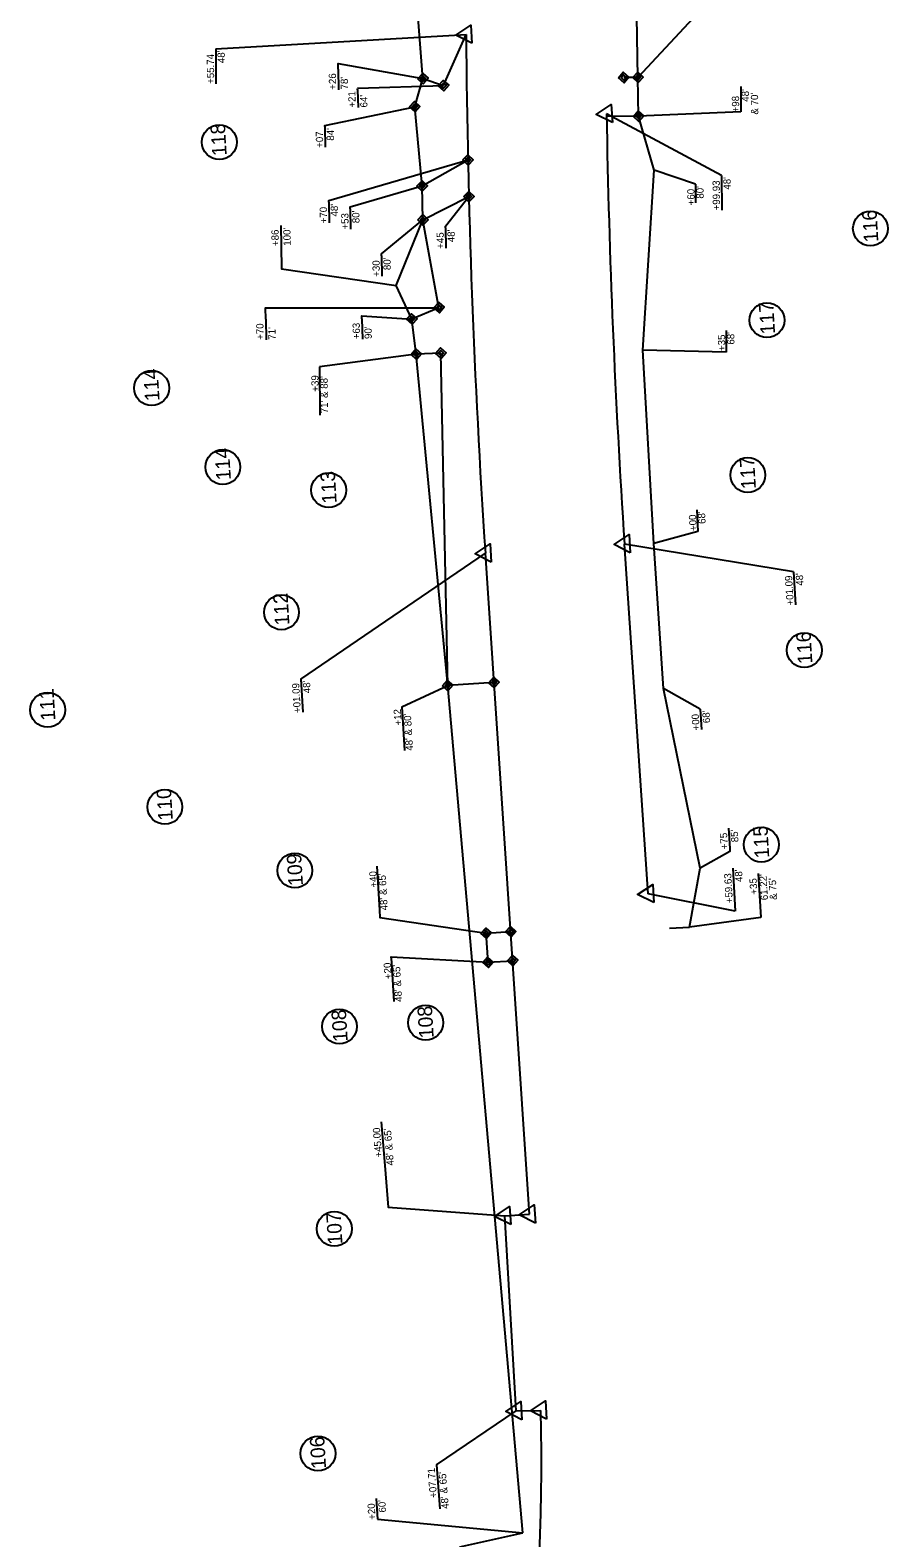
# Model space of a CAD drawing. Extents: x 2320946 to 2332748, y 597838 to 612698.
# Drawn here: x 2328037 to 2328627, y 604376 to 605414 of the extents above; entities that cross this region are included whole.
import ezdxf

# ---------------------------------------------------------------- set-up
doc = ezdxf.new("R2010")
doc.units = 0
for name, color, linetype in [('Prop Easement Construction', 7, 'Continuous'), ('Prop Easement Construction Station Offsets', 7, 'Continuous'), ('Prop Easement Permanent Drainage', 7, 'Continuous'), ('Prop Easement Permanent Drainage Station Offsets', 7, 'Continuous'), ('Prop Easement Permanent Drainage Utility', 7, 'Continuous'), ('Prop Easement Permanent Utility', 7, 'Continuous'), ('Prop Easement Permanent Utility Station Offsets', 7, 'Continuous'), ('Prop Parcel Number CELL', 7, 'Continuous'), ('Prop ROW Marker CELL', 7, 'Continuous'), ('Prop ROW Permanent Easement CELL', 7, 'Continuous'), ('Prop ROW RW Lines', 7, 'Continuous'), ('Prop ROW Station Offsets', 7, 'Continuous')]:
    doc.layers.add(name, color=color, linetype=linetype)

msp = doc.modelspace()

# ---------------------------------------------------------------- linework, layer by layer
at = {"layer": 'Prop Easement Construction'}
for p, q in [((2328455.1, 605381.6), (2328452.9, 605513.1)), ((2328307.1, 605380.8), (2328301.6, 605450.6)), ((2328466.3, 605317.6), (2328455.5, 605354.9)), ((2328458.5, 605193.8), (2328466.3, 605317.6)), ((2328209.2, 605279.6), (2328209.5, 605265.6)), ((2328288.6, 605238.2), (2328307.1, 605283.5)), ((2328299.4, 605215.2), (2328288.6, 605238.2)), ((2328324.1, 604962.9), (2328302.4, 605191)), ((2328465.9, 605060.6), (2328458.5, 605193.8)), ((2328472.6, 604960.8), (2328465.9, 605060.6)), ((2328375.8, 604379.4), (2328324.1, 604962.9)), ((2328497.9, 604837.2), (2328472.6, 604960.8)), ((2328490.5, 604796.6), (2328497.9, 604837.2)), ((2328476.8, 604795.7), (2328490.5, 604796.6)), ((2328332.4, 604369.8), (2328375.8, 604379.4))]:
    msp.add_line(p, q, dxfattribs=at)
msp.add_lwpolyline([(2328209.5, 605265.6), (2328209.8, 605249.7), (2328288.6, 605238.2)], dxfattribs=at)
at = {"layer": 'Prop Easement Construction Station Offsets'}
for p, q in [((2328494.6, 605308), (2328494.7, 605295.2)), ((2328515.7, 605207.4), (2328515.9, 605192.4)), ((2328515.9, 605192.4), (2328458.5, 605193.8)), ((2328495.5, 605083.9), (2328496.4, 605068.8)), ((2328496.4, 605068.8), (2328465.9, 605060.6)), ((2328498, 604946.6), (2328498.8, 604932.5)), ((2328517.5, 604864.6), (2328518.3, 604850.6)), ((2328537.8, 604833.4), (2328539.6, 604803.2)), ((2328274.9, 604403.1), (2328275.8, 604389))]:
    msp.add_line(p, q, dxfattribs=at)
for points in [[(2328494.6, 605308), (2328466.3, 605317.6)], [(2328498, 604946.6), (2328472.6, 604960.8)], [(2328518.3, 604850.6), (2328518.4, 604848.6), (2328497.9, 604837.2)], [(2328539.6, 604803.2), (2328490.5, 604796.6)], [(2328275.8, 604389), (2328375.8, 604379.4)]]:
    msp.add_lwpolyline(points, dxfattribs=at)
at = {"layer": 'Prop Easement Permanent Drainage'}
for p, q in [((2328455.1, 605381.6), (2328445.3, 605381.5)), ((2328455.5, 605354.9), (2328455.1, 605381.6)), ((2328455.5, 605354.9), (2328433.5, 605354.6)), ((2328350.5, 604792.3), (2328367.5, 604793.4)), ((2328351.9, 604772.3), (2328350.5, 604792.3)), ((2328351.9, 604772.3), (2328368.8, 604773.4))]:
    msp.add_line(p, q, dxfattribs=at)
at = {"layer": 'Prop Easement Permanent Drainage Station Offsets'}
for p, q in [((2328493, 605422.4), (2328455.1, 605381.6)), ((2328525.9, 605375.2), (2328526, 605357.9)), ((2328526, 605357.9), (2328455.5, 605354.9)), ((2328242.2, 605295.6), (2328242.4, 605281.4)), ((2328257, 605291), (2328257.2, 605277.1)), ((2328322.6, 605277.9), (2328322.8, 605263.9)), ((2328278.5, 605258.8), (2328278.7, 605244.6)), ((2328275.4, 604838.4), (2328277.2, 604808.3)), ((2328285.3, 604775.3), (2328287.1, 604745.2))]:
    msp.add_line(p, q, dxfattribs=at)
for points in [[(2328242.2, 605295.6), (2328242.2, 605296.8), (2328338.1, 605324.7)], [(2328257, 605291), (2328257, 605292.5), (2328306.5, 605306.8)], [(2328322.6, 605277.9), (2328322.6, 605279.1), (2328338.7, 605299.5)], [(2328278.5, 605258.8), (2328278.5, 605260.2), (2328307.1, 605283.5)], [(2328277.2, 604808.3), (2328277.5, 604803.2), (2328350.5, 604792.3)], [(2328285.3, 604775.3), (2328285.3, 604776.1), (2328351.9, 604772.3)]]:
    msp.add_lwpolyline(points, dxfattribs=at)
at = {"layer": 'Prop Easement Permanent Drainage Utility'}
for p, q in [((2328306.5, 605306.8), (2328338.1, 605324.7)), ((2328307.1, 605283.5), (2328306.5, 605306.8)), ((2328307.1, 605283.5), (2328338.7, 605299.5))]:
    msp.add_line(p, q, dxfattribs=at)
at = {"layer": 'Prop Easement Permanent Utility'}
for p, q in [((2328321.2, 605375.9), (2328336.8, 605411.1)), ((2328301.4, 605361.4), (2328307.1, 605380.8)), ((2328307.1, 605380.8), (2328321.2, 605375.9)), ((2328306.5, 605306.8), (2328301.4, 605361.4)), ((2328318.1, 605223), (2328307.1, 605283.5)), ((2328318.1, 605223), (2328299.4, 605215.2)), ((2328302.4, 605191), (2328299.4, 605215.2)), ((2328319.4, 605191.7), (2328302.4, 605191)), ((2328324.1, 604962.9), (2328319.4, 605191.7)), ((2328356, 604965), (2328324.1, 604962.9))]:
    msp.add_line(p, q, dxfattribs=at)
at = {"layer": 'Prop Easement Permanent Utility Station Offsets'}
for p, q in [((2328248.6, 605387.2), (2328248.9, 605373.1)), ((2328262.1, 605373.1), (2328262.4, 605360.8)), ((2328239.5, 605347.8), (2328239.7, 605333.6)), ((2328198.8, 605215.1), (2328199.1, 605200.9)), ((2328265.1, 605215.3), (2328265.4, 605201.4)), ((2328302.4, 605191), (2328235.8, 605182.2)), ((2328235.8, 605182.2), (2328236.1, 605148.9)), ((2328292.6, 604948.2), (2328294.4, 604918.1))]:
    msp.add_line(p, q, dxfattribs=at)
for points in [[(2328248.6, 605387.2), (2328248.6, 605391.1), (2328307.1, 605380.8)], [(2328262.1, 605373.1), (2328262.2, 605374.1), (2328321.2, 605375.9)], [(2328239.5, 605347.8), (2328239.5, 605348.4), (2328301.4, 605361.4)], [(2328198.8, 605215.1), (2328198.6, 605223), (2328318.1, 605223)], [(2328265.1, 605215.3), (2328265.1, 605217.5), (2328299.4, 605215.2)], [(2328292.6, 604948.2), (2328324.1, 604962.9)]]:
    msp.add_lwpolyline(points, dxfattribs=at)
at = {"layer": 'Prop Parcel Number CELL'}
for p, q in [((2328166.9, 605337), (2328166.9, 605337)), ((2328615.1, 605277.5), (2328615.1, 605277.5)), ((2328543.9, 605214.4), (2328543.9, 605214.4)), ((2328120.3, 605167.7), (2328120.3, 605167.7)), ((2328169.3, 605113.3), (2328169.3, 605113.3)), ((2328530.7, 605107.8), (2328530.7, 605107.8)), ((2328242.2, 605097.4), (2328242.2, 605097.4)), ((2328209.7, 605013.3), (2328209.7, 605013.3)), ((2328569.6, 604987.2), (2328569.6, 604987.2)), ((2328048.7, 604946.1), (2328048.7, 604946.1)), ((2328129.4, 604879.3), (2328129.4, 604879.3)), ((2328540, 604853.3), (2328540, 604853.3)), ((2328218.9, 604835.5), (2328218.9, 604835.5)), ((2328308.9, 604730.7), (2328308.9, 604730.7)), ((2328249.6, 604728.1), (2328249.6, 604728.1)), ((2328246.1, 604588.8), (2328246.1, 604588.8)), ((2328234.8, 604434.1), (2328234.8, 604434.1))]:
    msp.add_line(p, q, dxfattribs=at)
for centre in [(2328166.9, 605337), (2328615.1, 605277.5), (2328543.9, 605214.4), (2328120.3, 605167.7), (2328169.3, 605113.3), (2328530.7, 605107.8), (2328242.2, 605097.4), (2328209.7, 605013.3), (2328569.6, 604987.2), (2328048.7, 604946.1), (2328129.4, 604879.3), (2328540, 604853.3), (2328218.9, 604835.5), (2328249.6, 604728.1), (2328308.9, 604730.7), (2328246.1, 604588.8), (2328234.8, 604434.1)]:
    msp.add_circle(centre, 12, dxfattribs=at)
at = {"layer": 'Prop ROW Marker CELL'}
for p, q in [((2328336.8, 605411.1), (2328336.8, 605411.1)), ((2328307.1, 605380.8), (2328307.1, 605380.8)), ((2328321.2, 605375.9), (2328321.2, 605375.9)), ((2328445.3, 605381.5), (2328445.3, 605381.5)), ((2328455.1, 605381.6), (2328455.1, 605381.6)), ((2328301.4, 605361.4), (2328301.4, 605361.4)), ((2328433.5, 605356.5), (2328433.5, 605356.5)), ((2328455.5, 605354.9), (2328455.5, 605354.9)), ((2328338.1, 605324.7), (2328338.1, 605324.7)), ((2328306.5, 605306.8), (2328306.5, 605306.8)), ((2328338.7, 605299.5), (2328338.7, 605299.5)), ((2328307.1, 605283.5), (2328307.1, 605283.5)), ((2328318.1, 605223), (2328318.1, 605223)), ((2328299.4, 605215.2), (2328299.4, 605215.2)), ((2328302.4, 605191), (2328302.4, 605191)), ((2328319.4, 605191.7), (2328319.4, 605191.7)), ((2328350.1, 605053.9), (2328350.1, 605053.9)), ((2328445.9, 605060.3), (2328445.9, 605060.3)), ((2328324.1, 604962.9), (2328324.1, 604962.9)), ((2328356, 604965), (2328356, 604965)), ((2328462, 604819.4), (2328462, 604819.4)), ((2328350.5, 604792.3), (2328350.5, 604792.3)), ((2328367.5, 604793.4), (2328367.5, 604793.4)), ((2328351.9, 604772.3), (2328351.9, 604772.3)), ((2328368.8, 604773.4), (2328368.8, 604773.4)), ((2328363.5, 604597.7), (2328363.5, 604597.7)), ((2328380.5, 604598.8), (2328380.5, 604598.8)), ((2328371.3, 604463.4), (2328371.3, 604463.4)), ((2328388.3, 604463.8), (2328388.3, 604463.8))]:
    msp.add_line(p, q, dxfattribs=at)
for points in [[(2328340.8, 605405.1), (2328329.6, 605410.7), (2328340, 605417.6)], [(2328437.5, 605350.5), (2328426.3, 605356), (2328436.7, 605362.9)], [(2328449.8, 605054.3), (2328438.7, 605059.9), (2328449.1, 605066.8)], [(2328354, 605047.9), (2328342.9, 605053.5), (2328353.3, 605060.4)], [(2328465.9, 604813.4), (2328454.8, 604819), (2328465.2, 604825.8)], [(2328384.5, 604592.8), (2328373.3, 604598.4), (2328383.7, 604605.3)], [(2328367.5, 604591.7), (2328356.3, 604597.3), (2328366.7, 604604.2)], [(2328375.2, 604457.4), (2328364.1, 604463), (2328374.5, 604469.8)], [(2328392.2, 604457.8), (2328381.1, 604463.4), (2328391.5, 604470.3)]]:
    msp.add_lwpolyline(points, close=True, dxfattribs=at)
at = {"layer": 'Prop ROW Permanent Easement CELL'}
for points in [[(2328303.5, 605380.5), (2328306.9, 605384.3), (2328310.7, 605381), (2328307.3, 605377.2)], [(2328441.7, 605381.3), (2328445, 605385.1), (2328448.9, 605381.7), (2328445.5, 605377.9)], [(2328443.5, 605381.4), (2328445.2, 605383.3), (2328447.1, 605381.6), (2328445.4, 605379.7)], [(2328451.5, 605381.4), (2328454.9, 605385.2), (2328458.7, 605381.8), (2328455.3, 605378)], [(2328453.3, 605381.5), (2328455, 605383.4), (2328456.9, 605381.7), (2328455.2, 605379.8)], [(2328305.3, 605380.6), (2328307, 605382.6), (2328308.9, 605380.9), (2328307.2, 605379)], [(2328317.6, 605375.7), (2328321, 605379.5), (2328324.8, 605376.1), (2328321.4, 605372.3)], [(2328319.4, 605375.8), (2328321.1, 605377.7), (2328323, 605376), (2328321.3, 605374.1)], [(2328297.8, 605361.2), (2328301.2, 605365), (2328305, 605361.6), (2328301.6, 605357.8)], [(2328299.6, 605361.3), (2328301.3, 605363.2), (2328303.2, 605361.5), (2328301.5, 605359.6)], [(2328451.9, 605354.7), (2328455.3, 605358.5), (2328459.1, 605355.1), (2328455.7, 605351.3)], [(2328453.7, 605354.8), (2328455.4, 605356.7), (2328457.3, 605355), (2328455.6, 605353.1)], [(2328334.5, 605324.7), (2328338, 605328.3), (2328341.7, 605324.7), (2328338.1, 605321.1)], [(2328336.3, 605324.7), (2328338.1, 605326.5), (2328339.9, 605324.7), (2328338.1, 605322.9)], [(2328302.9, 605306.7), (2328306.5, 605310.4), (2328310.1, 605306.8), (2328306.5, 605303.2)], [(2328304.7, 605306.8), (2328306.5, 605308.6), (2328308.3, 605306.8), (2328306.5, 605305)], [(2328335.1, 605299.5), (2328338.7, 605303.1), (2328342.3, 605299.5), (2328338.7, 605295.9)], [(2328336.9, 605299.5), (2328338.7, 605301.3), (2328340.5, 605299.5), (2328338.7, 605297.7)], [(2328303.5, 605283.4), (2328307.1, 605287.1), (2328310.7, 605283.5), (2328307.1, 605279.9)], [(2328305.3, 605283.5), (2328307.1, 605285.3), (2328308.9, 605283.5), (2328307.1, 605281.7)], [(2328295.8, 605215), (2328299.2, 605218.8), (2328303, 605215.4), (2328299.6, 605211.6)], [(2328297.6, 605215.1), (2328299.3, 605217), (2328301.2, 605215.3), (2328299.5, 605213.4)], [(2328314.5, 605222.8), (2328317.9, 605226.6), (2328321.7, 605223.3), (2328318.4, 605219.5)], [(2328316.3, 605222.9), (2328318, 605224.8), (2328319.9, 605223.2), (2328318.2, 605221.3)], [(2328298.9, 605190.8), (2328302.2, 605194.6), (2328306, 605191.2), (2328302.7, 605187.4)], [(2328300.6, 605190.9), (2328302.3, 605192.8), (2328304.2, 605191.1), (2328302.6, 605189.2)], [(2328315.8, 605191.5), (2328319.2, 605195.3), (2328323, 605191.9), (2328319.6, 605188.1)], [(2328317.6, 605191.6), (2328319.3, 605193.5), (2328321.2, 605191.8), (2328319.5, 605189.9)], [(2328352.4, 604964.8), (2328355.8, 604968.6), (2328359.6, 604965.2), (2328356.2, 604961.4)], [(2328320.5, 604962.7), (2328323.9, 604966.5), (2328327.7, 604963.1), (2328324.3, 604959.3)], [(2328322.3, 604962.8), (2328324, 604964.7), (2328325.9, 604963), (2328324.2, 604961.1)], [(2328354.2, 604964.9), (2328355.9, 604966.8), (2328357.8, 604965.1), (2328356.1, 604963.2)], [(2328346.9, 604792.1), (2328350.3, 604795.9), (2328354.1, 604792.5), (2328350.7, 604788.7)], [(2328348.7, 604792.2), (2328350.4, 604794.1), (2328352.3, 604792.4), (2328350.6, 604790.5)], [(2328363.9, 604793.2), (2328367.3, 604797), (2328371.1, 604793.6), (2328367.7, 604789.8)], [(2328365.7, 604793.3), (2328367.4, 604795.2), (2328369.3, 604793.5), (2328367.6, 604791.6)], [(2328348.3, 604772.1), (2328351.6, 604775.9), (2328355.4, 604772.5), (2328352.1, 604768.7)], [(2328350.1, 604772.2), (2328351.7, 604774.1), (2328353.7, 604772.4), (2328352, 604770.5)], [(2328365.2, 604773.2), (2328368.6, 604777), (2328372.4, 604773.7), (2328369, 604769.9)], [(2328367, 604773.3), (2328368.7, 604775.2), (2328370.6, 604773.6), (2328368.9, 604771.7)]]:
    msp.add_lwpolyline(points, close=True, dxfattribs=at)
at = {"layer": 'Prop ROW RW Lines'}
for p, q in [((2328380.5, 604598.8), (2328350.1, 605053.9)), ((2328462, 604819.4), (2328445.9, 605060.3)), ((2328363.5, 604597.7), (2328380.5, 604598.8)), ((2328371.3, 604463.4), (2328363.5, 604597.7)), ((2328371.3, 604463.4), (2328388.3, 604463.8))]:
    msp.add_line(p, q, dxfattribs=at)
for centre, radius, start, end in [((2334374.6, 605456.5), 6038, 180.43036, 183.82261), ((2334374.6, 605456.5), 5942, 180.96413, 183.82261), ((2326986.7, 604429.2), 1402, 342.8521, 1.4123)]:
    msp.add_arc(centre, radius, start, end, dxfattribs=at)
at = {"layer": 'Prop ROW Station Offsets'}
for p, q in [((2328164.4, 605401.2), (2328336.8, 605411.1)), ((2328164.4, 605401.2), (2328164.6, 605377.2)), ((2328512.6, 605314.1), (2328512.8, 605290.2)), ((2328562.2, 605041.2), (2328563.6, 605018.5)), ((2328223, 604967.2), (2328224.3, 604944.5)), ((2328520.3, 604837.2), (2328522.1, 604807.6)), ((2328278.4, 604662.5), (2328280.8, 604632.4)), ((2328316.3, 604426.2), (2328318.7, 604396.1))]:
    msp.add_line(p, q, dxfattribs=at)
for points in [[(2328512.6, 605314.1), (2328433.5, 605356.5)], [(2328223, 604967.2), (2328350.1, 605053.9)], [(2328562.2, 605041.2), (2328445.9, 605060.3)], [(2328522.1, 604807.6), (2328462, 604819.4)], [(2328280.8, 604632.4), (2328283.1, 604603.6), (2328363.5, 604597.7)], [(2328316.3, 604426.2), (2328371.3, 604463.4)]]:
    msp.add_lwpolyline(points, dxfattribs=at)

# ---------------------------------------------------------------- texts
at = {"layer": 'Prop Easement Construction'}
for s, p in [('+86', (2328207.9, 605265.5)), ("100'", (2328216.1, 605265.7))]:
    msp.add_text(s, height=5, rotation=91.1657, dxfattribs=at).set_placement(p)
at = {"layer": 'Prop Easement Construction Station Offsets'}
for s, rotation, p in [('+60', 90.5483, (2328494.1, 605293.5)), ("80'", 90.5483, (2328500.3, 605298.1)), ('+35', 90.5483, (2328515.2, 605193.2)), ("68'", 90.5483, (2328521.5, 605197.6)), ("68'", 93.4385, (2328501.7, 605074.3)), ('+00', 93.4385, (2328495.7, 605069.4)), ('+00', 93.4385, (2328497.6, 604932.1)), ("68'", 93.4385, (2328504.8, 604937.1)), ('+75', 93.4368, (2328517.1, 604850.3)), ("85'", 93.4368, (2328524.3, 604855.1)), ('+35', 93.4385, (2328537.4, 604819)), ("61.22'", 93.4385, (2328544.6, 604815.2)), ("& 75'", 93.4385, (2328550.9, 604815.4)), ('+20', 93.4385, (2328274.5, 604388.6)), ("60'", 93.4385, (2328281.7, 604393.6))]:
    msp.add_text(s, height=5, rotation=rotation, dxfattribs=at).set_placement(p)
at = {"layer": 'Prop Easement Permanent Drainage Station Offsets'}
for s, rotation, p in [("48'", 90.5488, (2328531.5, 605364.8)), ('+98', 90.5488, (2328524.8, 605357.5)), ("& 70'", 90.5488, (2328537.9, 605356)), ('+70', 90.5471, (2328241.1, 605281.1)), ("48'", 90.5471, (2328248.6, 605285.8)), ("80'", 90.5471, (2328263.4, 605281.2)), ('+53', 90.5471, (2328255.9, 605276.8)), ('+45', 90.5471, (2328321.5, 605263.6)), ("48'", 90.5471, (2328329, 605268.1)), ('+30', 90.5471, (2328277.4, 605244.3)), ("80'", 90.5471, (2328284.9, 605248.9)), ('+40', 93.4368, (2328275.7, 604823.9)), ("48' & 65'", 93.4368, (2328282.9, 604808.2)), ('+20', 93.4368, (2328285.6, 604760.9)), ("48' & 65'", 93.4368, (2328292.8, 604745.2))]:
    msp.add_text(s, height=5, rotation=rotation, dxfattribs=at).set_placement(p)
at = {"layer": 'Prop Easement Permanent Utility Station Offsets'}
for s, rotation, p in [('+26', 91.1657, (2328247.4, 605373.1)), ("78'", 91.1657, (2328255.5, 605373.3)), ('+21', 91.1657, (2328260.8, 605360.8)), ("64'", 91.1657, (2328268.9, 605360.9)), ('+07', 90.5471, (2328238.4, 605333.1)), ("84'", 90.5471, (2328245.9, 605338)), ('+70', 91.1657, (2328197.5, 605200.9)), ("71'", 91.1657, (2328205.7, 605201)), ('+63', 91.1657, (2328263.8, 605201.3)), ("90'", 91.1657, (2328271.9, 605201.5)), ('+39', 90.5488, (2328235.3, 605165.2)), ("71' & 88'", 90.5488, (2328241.7, 605150.3)), ('+12', 93.4368, (2328292.5, 604935.5)), ("48' & 80'", 93.4368, (2328300.3, 604918.1))]:
    msp.add_text(s, height=5, rotation=rotation, dxfattribs=at).set_placement(p)
at = {"layer": 'Prop Parcel Number CELL'}
for s, p in [('118', (2328172, 605327.8)), ('116', (2328620.6, 605268.4)), ('117', (2328549.5, 605205)), ('114', (2328125.8, 605159)), ('114', (2328174.9, 605104.5)), ('117', (2328536.3, 605098.4)), ('113', (2328247.7, 605088.5)), ('112', (2328215.2, 605004.6)), ('116', (2328575.2, 604978)), ('111', (2328054.1, 604938.9)), ('110', (2328134.9, 604870.2)), ('115', (2328545.5, 604844.3)), ('109', (2328224.5, 604825.2)), ('108', (2328255.3, 604717.8)), ('108', (2328314.5, 604720.3)), ('107', (2328251.7, 604578.2)), ('106', (2328240.4, 604423.8))]:
    msp.add_text(s, height=10, rotation=93.4368, dxfattribs=at).set_placement(p)
at = {"layer": 'Prop ROW Station Offsets'}
for s, rotation, p in [('+55.74', 90.5488, (2328163.4, 605377.1)), ("48'", 90.5488, (2328170.7, 605391.4)), ('+99.93', 90.5488, (2328511.6, 605290)), ("48'", 90.5488, (2328518.9, 605304.3)), ('+01.09', 93.4385, (2328562.4, 605018.1)), ("48'", 93.4385, (2328569.1, 605031.7)), ('+01.09', 93.4385, (2328223.1, 604944.1)), ("48'", 93.4385, (2328229.8, 604957.7)), ('+59.63', 93.4385, (2328520.5, 604813.1)), ("48'", 93.4385, (2328527.2, 604827.7)), ('+45.00', 94.5682, (2328279.1, 604638.1)), ("48' & 65'", 94.5682, (2328287.1, 604632.5)), ('+07.71', 94.5682, (2328316.8, 604403.8)), ("48' & 65'", 94.5682, (2328324.9, 604396.2))]:
    msp.add_text(s, height=5, rotation=rotation, dxfattribs=at).set_placement(p)

doc.saveas('drawing.dxf')
